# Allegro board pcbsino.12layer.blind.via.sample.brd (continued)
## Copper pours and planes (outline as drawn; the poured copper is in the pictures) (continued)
VDD_1V8 on BOTTOM: 24.2,33.97 24.91,33.97 25.32,33.57 25.32,31.61 24.99,31.28 23.28,31.28 23.08,31.48 23.08,32.91 23.33,33.16 24.02,33.16 24.15,33.29 24.15,33.92
VDD_1V8 on PWR_L6: 34.94,56.1 38.52,56.1 38.96,55.66 38.96,53.2 38.98,53.2 40.66,51.52 48.51,51.52 48.91,51.12 48.91,50.05 48.48,49.62 39.64,49.62 38.96,48.93 38.96,29.05 36.87,26.96 30.7,26.96 28.82,28.84 26.99,28.84 26.53,28.38 26.53,27.65 26.15,27.27 25.62,27.27 25.26,27.62 25.26,30.42 26.28,31.43 29.53,31.43 30.45,30.52 34,30.52 34.61,31.13 34.61,33.44 33.65,34.4 33.65,49.29 34.36,50 34.36,55.49 34.35,55.5
VDD_1V8 on SIG_L10: 23.92,24.04 23.92,26.23 24.35,26.66 24.35,27.95 23.92,28.38 23.92,34.13 24.76,34.96 26.86,34.96 27.73,34.1 28.72,34.1 29.48,34.86 34.33,34.86 34.54,35.07 35.7,35.07 35.73,35.04 36.87,35.04 37.63,35.8 37.63,37.25 38.17,37.78 39.03,37.78 40.17,36.64 40.17,29.73 36.92,26.48 34.26,26.48 32.86,25.08 30.78,25.08 30.22,25.64 29.05,25.64 28.67,25.26 28.67,23.13 27.78,22.24 27.2,22.24 26.36,23.08 26.36,23.71 26.18,23.89 25.37,23.89 25.06,23.58 24.38,23.58
VDD_3V3 on TOP: 51.66,22.34 53.71,22.34 53.76,22.29 53.76,21.73 53.74,21.7 54.17,21.27 54.25,21.27 54.35,21.17 54.35,20.41 54.22,20.28 52.42,20.28 51.96,20.74 51.96,21.32 51.55,21.73 51.55,22.24
VDD_3V3 on TOP: 9.59,66.69 9.59,63.54 9.87,63.26 11.6,63.26 11.6,64.28 11.14,64.73 11.14,66.69 11.07,66.76 9.67,66.76
VDD_3V3 on TOP: 19.98,59.07 16.45,59.07 16.2,58.81 16.2,55.77 16.35,55.61 19.52,55.61 20.18,56.27 20.18,58.86
VDD_3V3 on BOTTOM: 51.22,20.84 45.15,20.84 42.74,18.43 42.74,17.67 43.07,17.34 43.65,17.34 44.14,17.82 44.14,18.68 44.82,19.37 49.29,19.37 49.55,19.11 51.02,19.11 51.6,19.7 51.6,20.46
VDD_3V3 on BOTTOM: 23.59,21.04 24.3,21.04 24.53,20.82 24.53,17.84 24.35,17.67 22.24,17.67 21.99,17.92 21.99,19.34 23.51,20.87 23.51,20.97
VDD_3V3 on BOTTOM: 21.15,7.66 21.15,5.12 21.3,4.97 21.89,4.97 22.17,4.69 22.17,3.11 22.24,3.04 23.46,3.04 23.72,3.29 23.72,3.87 23.56,4.03 23.08,4.03 23,4.1 23,4.86 23.11,4.97 23.54,4.97 23.77,5.19 23.77,5.86 27.91,5.86 28.26,6.21 28.26,8.19 28.69,8.62 28.69,9.21 28.36,9.54 27.86,9.54 27.73,9.66 27.73,10.05 27.86,10.17 27.86,10.68 27.68,10.86 25.42,10.86 24.91,11.37 24.91,11.85 24.68,12.08 23.97,12.08 23.64,11.75 23.64,7.63 23.46,7.46 22.27,7.46 21.96,7.76 21.25,7.76
VDD_3V3 on BOTTOM: 45.08,40.25 43.02,40.25 42.66,39.89 42.66,37.99 42.92,37.73 43.48,37.73 43.6,37.86 43.6,38.39 43.96,38.75 45.1,38.75 45.23,38.88 45.23,40.09
VDD_3V3 on BOTTOM: 33.52,23.41 35.04,23.41 35.45,23.81 35.45,24.88 35.6,25.03 35.96,25.03 36.62,24.37 36.62,23.79 36.52,23.69 36.26,23.69 36.09,23.51 36.09,22.9 36.47,22.52 36.47,20.18 36.36,20.08 33.6,20.08 33.19,20.49 33.19,23.08
VDD_3V3 on BOTTOM: 20.74,59.12 16.32,59.12 16.27,59.07 16.27,55.99 16.37,55.89 17.75,55.89 18.76,56.91 20.77,56.91 20.95,57.09 20.95,58.92
VDD_3V3 on INT_L3: 26.79,6.59 24.83,8.55 24.83,10.45 24.93,10.55 25.44,10.55 26.15,11.27 28.82,11.27 30.7,9.39 30.7,8.57 30.4,8.27 28.24,8.27 27.91,8.6 27.91,9.92 27.47,10.35 26.31,10.35 26.13,10.17 26.13,8.14 26.61,7.66 27.37,7.66 27.83,7.2 27.83,6.82 27.6,6.59
VDD_3V3 on INT_L3: 13.2,65.6 9.16,65.6 8.3,64.73 8.3,60.08 8.81,59.58 12.23,59.58 12.26,59.6 15.89,55.97 15.89,55.89 19.4,55.89 19.93,56.43 19.93,58.86
VDD_3V3 on INT_L3: 31.44,31.56 34.31,31.56 34.51,31.36 34.51,30.82 35.5,29.83 37.74,29.83 38.55,30.65 39.26,30.65 39.41,30.49 39.41,29.76 39.06,29.4 39.06,28.64 38.63,28.21 38.63,27.8 38.7,27.72 42.08,27.72 42.89,26.91 42.89,22.85 42.31,22.26 40.86,22.26 40.38,22.75 40.38,23.18 39.31,24.24 38.63,24.24 38.22,24.65 38.22,26.1 37.94,26.38 37.15,26.38 36.64,26.89 35.07,26.89 33.27,25.08 33.27,22.7 32.35,21.78 29.43,21.78 29.15,22.06 29.15,23.38 29.4,23.64 30.17,23.64 30.4,23.86 30.4,25.39 29.96,25.82 28.9,25.82 28.31,25.24 28.31,22.8 27.75,22.24 25.21,22.24 25.06,22.39 25.06,23.41 24.43,24.04 24.43,26.56 24.68,26.81 24.68,27.5 23.99,28.18 23.99,31.94 24.43,32.37 25.34,32.37 26.03,31.69 28.82,31.69 29.4,32.27 31.16,32.27 31.34,32.09 31.34,31.66
VDD_3V3 on SIG_L5: 38.12,32.83 38.12,29.78 38.55,29.35 40.56,29.35 41.09,28.82 41.09,27.6 41.47,27.22 42.46,27.22 42.71,27.47 42.71,31.84 41.9,32.65 39.56,32.65 39.18,33.03 38.32,33.03
VDD_3V3 on PWR_L6: 8.3,1.84 8.3,4.03 9.42,5.14 15.43,5.14 17.64,7.35 17.64,18.2 18.66,19.22 22.9,19.22 23.56,19.88 23.56,20.71 24.2,21.35 24.91,21.35 27.25,23.69 29.43,23.69 31.89,21.22 36.69,21.22 38.07,22.59 43.88,22.59 45.53,24.24 45.53,35.29 45.23,35.6 45.23,36.41 45.53,36.72 45.53,46.37 49.52,50.36 49.52,51.4 49.72,51.6 49.72,51.63 53.26,51.63 53.53,51.35 53.53,18.35 52.75,17.56 47.46,17.56 45.64,15.74 45.64,11.6 47.41,9.82 47.41,4.1 45.95,2.64 36.35,2.64 34.74,1.03 34.74,0.64 34.48,0.38 33.65,0.38 32.74,1.28 8.86,1.28
VDD_3V3 on SIG_L8: 15.74,59.45 15.74,55.77 16.4,55.11 23.23,55.11 23.33,55.21 28.13,55.21 30.62,52.72 33.77,52.72 38.84,57.79 40.75,57.79 40.76,57.8 40.81,57.8 41.19,57.42 41.19,55.41 36.44,50.66 36.44,43.27 33.82,40.65 33.82,35.45 34.36,34.91 36.92,34.91 37.02,35.01 37.02,37.4 39.23,39.61 39.23,50.2 42.66,53.63 49.57,53.63 50.11,53.1 50.11,48.78 52.21,46.67 52.21,44.82 50.54,43.14 44.72,43.14 43.17,41.59 43.17,37.12 43.45,36.84 49.98,36.84 51.45,35.37 54.35,35.37 55.74,36.77 55.74,61.07 52.47,64.35 52.47,65.39 51.22,66.64 46.32,66.64 44.57,64.88 30.07,64.88 25.19,60.01 16.3,60.01
VDD_3V3 on SIG_L10: 26.74,6.16 23.87,9.03 23.87,10.33 24.12,10.58 25.82,10.58 26.15,10.25 26.15,9.18 28.06,7.28 28.06,6.36 27.86,6.16
VDD_CORE on TOP: 36.03,65.49 36.03,62.62 36.52,62.14 41.7,62.14 42.74,61.1 43.63,61.1 43.96,61.43 43.96,64.91 43.35,65.52 41.39,65.52 41.04,65.16 38.6,65.16 37.96,65.8 36.34,65.8
VDD_CORE on BOTTOM: 31.74,28.97 33.67,28.97 33.82,28.82 33.82,27.93 33.65,27.75 31.74,27.75 31.61,27.88 31.61,28.84
VDD_CORE on BOTTOM: 34.99,31.61 36.11,31.61 36.29,31.43 36.29,30.21 36.39,30.11 36.8,30.11 36.85,30.06 36.85,29.45 36.64,29.25 35.78,29.25 35.32,29.71 35.32,29.76 34.69,30.39 34.69,31.31
VDD_CORE on PWR_L7: 27.6,14.19 25.75,16.04 25.75,29.55 26.46,30.26 27.22,30.26 28.62,31.66 38.75,31.66 39.62,30.8 39.62,25.69 39.16,25.24 35.04,25.24 34.87,25.41 34.87,26.63 34.23,27.27 31.06,27.27 30.73,26.94 30.73,24.17 31.36,23.53 31.36,21.65 32.45,20.56 43.76,20.56 46.35,23.15 46.35,52.26 37.56,61.05 37.56,66.36 37.96,66.36 40,65.22 42.03,66.36 43.37,66.36 52.7,57.04 52.7,17.54 49.34,14.19
VDD_CORE on SIG_L8: 30.88,31.81 26.99,31.81 26,30.82 26,16.62 27.02,15.61 33.85,15.61 34.21,15.96 34.21,17.13 32.66,18.68 32.66,30.04
VDD_DSP on TOP: 20.87,66.99 27.55,66.99 28.29,66.26 28.29,63.26 28.06,63.03 26.36,63.03 24.86,64.53 21.33,64.53 20.49,65.37 20.49,66.61
VDD_DSP on BOTTOM: 32.07,26.86 34.36,26.86 34.54,26.68 34.54,25.24 34.31,25.01 33.85,25.01 33.77,24.93 33.77,24.6 33.49,24.32 31.74,24.32 31.41,24.65 31.41,25.97 31.56,26.12 31.89,26.12 31.97,26.2 31.97,26.76
VDD_DSP on BOTTOM: 20.82,66.82 27.53,66.82 28.29,66.05 28.29,63.44 27.88,63.03 26.2,63.03 25.57,63.67 25.57,64.35 25.44,64.48 21.76,64.48 20.69,65.55 20.69,66.69
VDD_DSP on PWR_L7: 31.23,27.14 34.08,27.14 34.64,26.58 34.64,25.21 34.82,25.03 39.54,25.03 39.95,25.44 39.95,37.24 40,49.52 29.02,60.49 18.31,60.49 16.65,62.14 16.65,66.79 16.98,67.12 31.13,67.12 46.07,52.18 46.07,23.33 43.65,20.92 32.66,20.92 31.54,22.03 31.54,23.74 30.93,24.35 30.93,26.84
VDD_GPU on TOP: 20.44,64.96 17.06,64.96 16.1,64 16.1,62.5 16.22,62.37 17.24,62.37 17.95,63.08 20.49,63.08 20.59,63.18 20.59,64.81
VDD_GPU on BOTTOM: 20.82,64.81 16.68,64.81 15.79,63.92 15.79,62.45 20.41,62.45 20.95,62.98 20.95,64.68
VDD_GPU on BOTTOM: 34.38,33.21 34.38,31.61 33.62,30.85 32.5,30.85 32.48,30.87 32.48,32.32 32.61,32.45 33.06,32.45 33.27,32.65 33.27,33.13 33.37,33.24 34.36,33.24
VDD_GPU on PWR_L6: 20.57,64.73 16.48,64.73 15.74,64 15.74,60.41 18.51,57.65 18.51,54.12 29.15,43.47 29.15,33.9 29.81,33.24 29.81,31.79 30.83,30.77 33.82,30.77 34.56,31.51 34.56,33.11 33.29,34.38 33.29,46.16 23.64,55.82 23.64,61.66
VDD_IVA on TOP: 16.25,55.21 16.25,52.77 17.37,51.65 17.37,50.58 17.75,50.2 19.52,50.2 19.98,50.66 19.98,53.78 19.32,54.45 18.43,54.45 17.72,55.16 17.72,55.18 17.57,55.33 16.37,55.33
VDD_IVA on BOTTOM: 18.25,53.78 20.95,53.78 21.2,53.53 21.2,52.13 20.79,51.73 16.81,51.73 16.04,52.49 16.04,54.37 16.35,54.67 16.35,55.39 16.48,55.51 17.62,55.51 17.85,55.28 17.85,54.19
VDD_IVA on BOTTOM: 26.33,31.79 27.42,31.79 27.7,31.51 27.7,29.96 27.53,29.78 26.92,29.78 26.79,29.91 26.79,30.26 26.51,30.54 26.2,30.54 26.05,30.7 26.05,31.51
VDD_IVA on PWR_L7: 24.58,30.34 26.15,30.34 26.37,30.56 27.11,30.56 28.67,32.12 28.67,47.71 20.95,55.44 16.43,55.44 16.04,55.05 16.04,51.22 19.91,47.36 22.37,47.36 23.63,46.1 23.63,43.64 24.32,42.94 24.32,30.59
VDD_IVA on SIG_L10: 25.06,47.08 25.06,46.29 25.47,45.89 26.43,45.89 26.53,45.99 26.53,46.83 26.15,47.21 25.19,47.21
VDD_MPU on TOP: 34.79,48.04 34.79,45.43 35.09,45.12 40.5,45.12 40.83,45.45 40.83,48.02 40.53,48.32 35.07,48.32
VDD_MPU on BOTTOM: 26.94,28.61 27.58,28.61 28.87,27.32 28.87,27.06 29.02,26.91 29.86,26.91 30.04,26.73 30.04,25.03 29.96,24.96 29.51,24.96 29.18,25.29 29.18,25.34 28.59,25.34 28.31,25.06 28.31,24.7 28.29,24.68 27.5,24.68 27.35,24.83 27.35,25.16 27.14,25.36 26.79,25.36 26.66,25.49 26.66,28.33
VDD_MPU on BOTTOM: 35.81,49.19 41.04,49.19 41.19,49.04 41.19,48.27 40.56,47.64 40.56,42.79 40.33,42.56 39.03,42.56 37.99,43.6 37.99,44.82 37.89,44.92 35.96,44.92 35.45,45.43 35.45,48.83
VDD_MPU on PWR_L6: 26.38,26.89 26.38,24.78 27.27,23.89 29.71,23.89 31.94,21.65 36.67,21.65 37.74,22.72 43.48,22.72 45.33,24.57 45.33,35.27 45.08,35.52 45.08,36.51 45.33,36.77 45.33,47.77 44.14,48.96 39.87,48.96 39.21,48.3 39.21,28.94 37.13,26.86 30.47,26.86 28.72,28.61 27.09,28.61 26.59,28.11 26.59,27.09
VDD_RTC on SIG_L8: 29.02,34.86 29.79,34.86 30.22,35.29 30.22,38.47 35.48,43.73 35.48,51.04 39.39,54.95 40.2,54.95 40.61,55.36 40.61,56.5 39.95,57.16 38.68,57.16 33.34,51.83 33.34,44.56 28.34,39.56 28.34,35.55
VDD_SD on BOTTOM: 35.45,33.29 35.45,32.04 35.58,31.92 37.46,31.92 37.76,32.22 38.07,32.22 40.33,34.48 40.33,34.84 40.5,35.01 42.13,35.01 42.33,35.22 42.33,36.26 41.93,36.67 40.07,36.67 39.87,36.46 38.85,36.46 37.02,34.63 37.02,33.97 36.54,33.49 35.65,33.49
VDD_SD on PWR_L6: 41.24,58.86 34,58.86 32.83,57.7 32.83,56.12 33.14,55.82 34.59,55.82 35.12,56.35 40.17,56.35 44.39,52.13 48.91,52.13 49.22,52.44 49.22,53.73 48.53,54.42 45.69,54.42
VDD_SD on SIG_L8: 49.45,52.87 42.87,52.87 39.92,49.92 39.92,36 40.78,35.14 42.33,35.14 42.99,35.8 42.99,46.14 42.31,46.83 42.31,48.81 43.1,49.59 47.54,49.59 49.6,51.65 49.6,52.72
VDDA_1V8_PHY_LDO3 on BOTTOM: 24.86,49.26 23.87,49.26 22.75,48.15 22.75,45.45 22.98,45.23 24.25,45.23 24.43,45.4 24.43,47.03 25.06,47.66 25.42,47.66 25.47,47.71 25.47,48.65
VDDA_1V8_PHY_LDO3 on INT_L3: 28.34,52.16 27.17,52.16 24.91,49.9 23.92,49.9 23.79,49.77 23.79,48.4 23.87,48.32 25.93,48.32 27.55,49.95 28.16,49.95 28.59,50.38 28.59,51.91
VDDA_1V8_PHY_LDO3_F on BOTTOM: 24.81,44.03 23.31,44.03 23.23,43.96 23.23,41.24 23.61,40.86 25.67,40.86 25.8,40.98 25.8,43.04
VDDA_1V8_PHY_LDO3_F on INT_L3: 24.63,42.94 24.63,42.35 30.14,36.84 30.14,32.75 30.5,32.4 31.23,32.4 31.51,32.12 31.51,31.79 31.61,31.69 32.22,31.69 33.27,32.73 33.27,36 30.01,39.26 28.92,39.26 27.09,41.08 27.09,42.08 25.98,43.19 24.88,43.19
VDDA_1V8_PHY_LDO4 on BOTTOM: 20.57,47.82 20.57,48.6 22.29,50.33 24.83,50.33 25.49,49.67 26.56,49.67 27.04,50.15 27.04,50.89 27.42,51.27 28.13,51.27 28.26,51.14 28.26,49.29 27.78,48.81 25.44,48.81 24.83,49.42 23.84,49.42 22.14,47.71 20.67,47.71
VDDA_1V8_PHY_LDO4_F on BOTTOM: 20.29,46.5 21.4,46.5 21.63,46.27 21.63,43.4 20.92,42.69 20.92,41.87 20.67,41.62 19.91,41.62 19.6,41.92 19.6,43.04 19.98,43.42 19.98,46.19
VDDA_1V8_PHY_LDO4_F on SIG_L8: 20.21,42.43 18.36,42.43 17.9,41.97 17.9,36 21.76,32.14 31.21,32.14 31.44,32.37 31.44,33.34 30.42,34.35 27.53,34.35 27.07,34.81 22.88,34.81 21.1,36.59 21.1,41.54
VDDA_1V8_PLL on BOTTOM: 39.01,42.3 39.01,41.44 39.11,41.34 42,41.34 42.38,41.72 42.38,42.84 42.23,42.99 41.44,42.99 40.89,42.43 39.13,42.43
VDDA_1V8_PLL on SIG_L10: 28.31,36.64 28.31,48.96 37.13,57.77 43.32,57.77 43.4,57.7 43.4,57.09 42.49,56.17 38.02,56.17 36.53,54.69 36.53,52.5 35.58,51.55 34.18,51.55 30.19,47.56 30.19,44.82 29.23,43.85 29.23,37.25 28.95,36.97 28.95,36.64 28.82,36.51 28.44,36.51
VDDA_1V8_PLL_F on BOTTOM: 39.11,40.15 40.3,40.15 40.43,40.02 40.43,37.17 39.79,36.54 39.16,36.54 38.9,36.79 38.9,39.94
VDDA_1V8_PLL_F on BOTTOM: 27.63,29.68 27.63,28.72 28.64,27.7 29.68,27.7 30.27,28.28 31.23,28.28 31.34,28.38 31.34,28.92 31.18,29.07 30.5,29.07 30.19,28.77 28.69,28.77 28.39,29.07 28.39,29.38 27.98,29.78 27.73,29.78
VDDA_1V8_PLL_F on GND_L11: 27.75,29.83 28.13,29.83 28.64,29.32 31.84,29.32 38.63,36.11 38.63,37.91 39.03,38.32 40.33,38.32 40.4,38.24 40.4,34.63 32.76,26.99 28.8,26.99 27.6,28.18 27.6,29.68
VDDS_DDR on TOP: 2.2,41.69 2.2,39.94 2.71,39.43 6.47,39.43 6.52,39.48 6.52,41.06 5.78,41.8 2.3,41.8
VDDS_DDR on TOP: 11.68,60.95 11.68,60.34 11.37,60.03 9.36,60.03 9.34,60.06 8.02,58.74 8.02,53.35 7.43,52.77 3.85,52.77 3.4,52.31 3.4,50.25 3.93,49.72 16.48,49.72 16.68,49.92 16.68,51.58 15.71,52.54 12.03,52.54 11.19,53.38 11.19,58.38 12.08,59.27 12.08,61 12.03,61.05 11.78,61.05
VDDS_DDR on TOP: 12.89,8.78 14.83,8.78 15.05,8.55 15.05,6.41 14.62,5.98 12.06,5.98 11.85,6.19 11.85,7.73
VDDS_DDR on TOP: 21.4,47.82 21.4,45.07 21.73,44.74 26.46,44.74 26.46,47.77 26.1,48.12 21.71,48.12
VDDS_DDR on TOP: 2.1,19.47 2.1,17.08 2.51,16.68 16.53,16.68 17.06,17.21 17.06,19.37 16.48,19.95 13,19.95 12.36,19.32 10.3,19.32 9.06,18.07 6.8,18.07 6.06,18.81 4.92,18.81 4.18,19.55 2.18,19.55
VDDS_DDR on BOTTOM: 23.92,26.48 23.92,25.87 24.07,25.72 25.29,25.72 25.72,26.15 25.72,26.51 25.62,26.61 24.05,26.61
VDDS_DDR on BOTTOM: 24.99,35.37 24.99,34.33 24.86,34.2 24.12,34.2 24.02,34.3 24.02,35.09 24.38,35.45 24.91,35.45
VDDS_DDR on BOTTOM: 25.65,23.69 23.89,23.69 23.28,23.08 23.28,22.14 23.46,21.96 23.89,21.96 24.27,22.34 24.27,22.62 24.5,22.85 25.59,22.85 25.82,23.08 25.82,23.51
VDDS_DDR on BOTTOM: 8.3,44.41 16.17,44.41 16.88,43.7 16.88,37.78 16.17,37.07 16.17,32.58 17.54,31.2 17.54,29.73 15,27.19 15,26.86 13.91,25.77 8.2,25.77 7.97,26 7.97,27.39 9.77,29.2 9.77,33.16 10.56,33.95 10.56,36.13 10.13,36.56 9.52,36.56 9.44,36.64 9.44,39.79 9.59,39.94 9.59,42.53 9.44,42.69 8.25,42.69 8.04,42.89 8.04,44.16
VDDS_DDR on BOTTOM: 9.19,5.8 14.39,5.8 15.05,6.46 15.05,8.83 15.03,8.85 10.38,8.85 9.82,8.29 9.82,6.87 9.54,6.59 9.06,6.59 8.91,6.44 8.91,6.08
VDDS_DDR on BOTTOM: 8.42,21.22 17.52,21.22 18.36,22.06 19.12,22.06 19.37,21.81 19.37,18.38 17.34,16.35 17.34,7.73 17.31,7.71 9.85,7.71 9.69,7.86 9.69,8.12 8.81,9 8.81,9.61 8.93,9.74 9.29,9.74 9.72,10.17 9.72,11.11 10.08,11.47 11.29,11.47 11.9,12.08 11.9,13.91 11.47,14.34 10.38,14.34 9.72,15 9.72,18.76 8.17,20.31 8.17,20.97
VDDS_DDR on INT_L3: 23.69,23.33 23.66,23.33 23.28,22.95 23.28,22.57 23.74,22.11 24.05,22.11 24.53,22.59 24.53,22.64 24.6,22.72 24.83,22.72 24.96,22.85 24.96,23.25 24.68,23.53 23.89,23.53
VDDS_DDR on INT_L3: 24.3,34.89 24.3,33.74 26.15,31.89 28.47,31.89 29.05,32.47 29.05,33.31 28.13,34.23 27.58,34.23 26.61,35.19 26.61,35.22 24.63,35.22
VDDS_DDR on INT_L3: 21.51,47.69 21.51,45.81 22.78,44.54 23.72,44.54 23.84,44.67 23.84,47.49 23.41,47.92 21.73,47.92
VDDS_DDR on PWR_L6: 4.79,57.01 2.2,54.42 2.2,7.15 3.52,5.83 14.85,5.83 17.16,8.14 17.16,18.73 17.9,19.47 22.65,19.47 23.28,20.1 23.28,20.97 23.91,21.59 24.77,21.59 26,22.82 26,26.66 25.11,27.55 25.11,30.59 26.26,31.74 29.38,31.74 29.56,31.92 29.56,32.98 28.8,33.74 28.8,43.27 17.64,54.42 14.55,54.42 11.96,57.01
VDDS_DDR on SIG_L10: 24.02,23.38 23.74,23.38 23.44,23.08 23.44,22.34 23.64,22.14 24.5,22.14 25.14,22.77 25.75,22.77 25.82,22.85 25.82,23.2 25.65,23.38 25.34,23.38 25.14,23.18 24.22,23.18
ETH0_DVDD33 on BOTTOM: 45.71,39.79 45.71,36.44 46.4,35.75 49.06,35.75 49.12,35.8 49.12,36.18 48.76,36.54 47.92,36.54 47.13,37.33 47.13,39.31 46.47,39.97 45.89,39.97
ETH0_VDD10 on BOTTOM: 49.72,29.96 47.72,29.96 47.16,29.4 44.8,29.4 44.57,29.17 44.57,28.05 44.72,27.9 47.18,27.9 47.74,27.34 48.81,27.34 49.8,28.33 49.8,29.88
ETH0_VDDREG33 on BOTTOM: 46.12,35.14 47.16,35.14 47.26,35.04 47.26,33.08 47.49,32.86 48.15,32.86 48.2,32.8 48.2,32.07 48.12,31.99 46.02,31.99 45.86,32.14 45.86,34.89
ETH1_AVDD33 on BOTTOM: 49.57,18.68 49.57,16.24 49.72,16.09 50.79,16.09 50.94,16.24 50.94,16.6 51.12,16.78 52.11,16.78 52.37,16.52 52.37,14.95 53.08,14.24 53.08,12.41 52.39,11.72 52.39,11.14 52.44,11.09 53.23,11.09 53.94,11.8 53.94,16.35 52.52,17.77 51.12,17.77 50.56,18.33 50.56,18.78 50.51,18.83 49.72,18.83
ETH1_DVDD10 on BOTTOM: 46.35,18.78 49.01,18.78 49.09,18.71 49.09,17.59 48.91,17.41 46.42,17.41 46.22,17.62 46.22,18.66
ETH1_VDD10 on TOP: 39.11,8.37 43.3,8.37 43.65,8.01 43.65,6.9 43.3,6.54 37.99,6.54 37.79,6.74 37.79,7.86 37.86,7.94 38.68,7.94
ETH1_VDD10 on INT_L3: 38.19,7.28 38.19,6.57 38.47,6.29 41.55,6.29 42.31,7.05 44.98,7.05 45.58,6.44 46.52,6.44 46.63,6.54 46.63,7.79 46.45,7.96 38.88,7.96
ETH1_VDDREG33 on BOTTOM: 46.5,13.58 45.89,13.58 45.71,13.4 45.71,9.92 45.89,9.74 46.55,9.74 47.06,10.25 47.06,12.54 46.6,12.99 46.6,13.48
LDO_VRTC on TOP: 37.3,54.12 38.75,54.12 39.08,54.45 39.08,55.18 38.8,55.46 38.35,55.46 37.91,55.03 37.25,55.03 36.97,54.75 36.97,54.45
LDO_VRTC on BOTTOM: 32.55,40.73 32.55,37.43 31.67,36.54 31.67,35.27 31.26,34.86 30.7,34.86 30.5,35.07 30.5,36.69 31.59,37.78 31.59,40.73 31.69,40.83 32.45,40.83
LDO_VRTC on SIG_L8: 30.8,35.5 32.22,35.5 33.34,34.38 33.34,31.43 35.48,29.3 35.48,19.75 37.91,17.31 37.91,5.14 37.66,4.89 36.77,4.89 36.62,5.04 36.62,16.35 33.9,19.06 33.9,29.1 32.2,30.8 32.2,33.87 31.56,34.51 30.75,34.51 30.62,34.63 30.62,35.32
LDO_VRTC on SIG_L10: 38.22,55 39.21,55 39.39,54.83 39.39,53.48 36.75,50.84 36.06,50.84 34.41,49.19 34.41,46.8 31.21,43.6 31.21,41.9 32.38,40.73 32.38,40.37 32.05,40.04 31.31,40.04 29.51,41.85 29.51,43.83 33.27,47.59 33.27,49.24 38.09,54.06 38.09,54.88
SMPS1_SW on TOP: 32.5,52.44 32.15,52.44 32.05,52.34 32.05,49.21 32.5,48.76 33.49,48.76 33.7,48.96 33.7,49.49 33.55,49.64 33.14,49.64 32.66,50.13 32.66,52.29
SMPS1_SW on BOTTOM: 33.98,49.62 31.94,49.62 31.69,49.37 31.69,45.5 31.92,45.28 33.95,45.28 34.18,45.5 34.18,49.42
SMPS2_SW on TOP: 31.18,52.44 31.18,49.85 30.73,49.39 30.73,45.56 31.03,45.25 33.24,45.25 33.44,45.45 33.44,47.87 33.01,48.3 32.3,48.3 31.82,48.78 31.82,52.44 31.74,52.51 31.26,52.51
SMPS3_SW on TOP: 28.74,52.39 28.74,49.77 27.32,48.35 27.32,45.45 27.65,45.12 29.58,45.12 30.22,45.76 30.22,48.98 29.53,49.67 29.53,52.36 29.4,52.49 28.85,52.49
SMPS4_SW on TOP: 30.34,58.46 30.34,62.04 29.33,63.06 29.33,65.85 29.48,66 31.46,66 31.69,65.77 31.69,61.91 31.11,61.33 31.11,58.43 31.03,58.36 30.45,58.36
SMPS5_SW on TOP: 29.56,58.46 29.56,60.52 29.23,60.85 29.23,61.76 29.35,61.89 29.96,61.89 30.17,61.68 30.17,58.41 30.14,58.38 29.63,58.38
SMPS5_SW on BOTTOM: 29.53,66.43 31.49,66.43 31.69,66.23 31.69,61.76 30.45,60.52 29.58,60.52 29.33,60.77 29.33,66.23
SMPS6_SW on TOP: 25.37,57.42 26.92,57.42 27.04,57.29 27.04,56.68 26.99,56.63 24.78,56.63 23.99,57.42 23.99,57.82 23.13,58.69 21.78,58.69 21.23,59.25 18.08,59.25 17.54,59.78 17.54,61.91 17.67,62.04 21.45,62.04 21.76,61.74 21.76,61 22.14,60.62 23.59,60.62 24.78,59.42 24.78,58
SMPS7_SW on TOP: 32.73,58.48 32.73,61.48 32.12,62.09 32.12,65.95 32.17,66 34.41,66 34.56,65.85 34.56,63.08 33.6,62.12 33.6,58.53 33.44,58.38 32.83,58.38
SMPS8_SW on TOP: 26.92,53.45 23.54,53.45 23.05,53.94 21.33,53.94 21.1,53.71 21.1,50.79 21.35,50.53 23.16,50.53 23.36,50.74 23.36,52.03 23.94,52.62 26.89,52.62 27.02,52.74 27.02,53.35
SMPS9_SW on TOP: 21.25,58.38 21.25,55.46 21.66,55.05 26.76,55.05 26.97,55.26 26.97,55.54 26.71,55.79 24.76,55.79 23.51,57.04 23.51,57.93 22.98,58.46 21.33,58.46
VREF_DDR on TOP: 13.25,63.56 13.25,64.4 13.5,64.66 14.06,64.66 14.47,65.06 14.47,65.65 14.55,65.72 16.5,65.72 16.68,65.55 16.68,64.88 16.22,64.43 15.66,64.43 14.93,63.69 13.81,63.69 13.58,63.46 13.35,63.46
VREF_DDR on SIG_L5: 26.76,34.02 27.42,34.02 27.75,33.69 27.75,28.87 26.92,28.03 26.92,27.57 25.85,26.51 23.94,26.51 23.56,26.89 23.56,27.42 23.72,27.57 24.25,27.57 25.7,29.02 25.7,31.46 26.64,32.4 26.64,33.9
VREF_DDR on PWR_L7: 16.68,65.62 8.4,65.62 6.54,63.77 6.54,58.26 6.82,57.98 6.82,45.58 5.53,44.29 5.53,9.61 6.7,8.45 9.52,8.45 11.14,10.07 11.14,20.46 15.77,25.08 24.38,25.08 24.96,25.67 24.96,28.69 23.94,29.71 12.21,29.71 11.27,30.65 11.27,62.83 11.7,63.26 16.5,63.26 16.91,63.67 16.91,65.39
VSYS_5V0 on TOP: 52.54,63.08 52.54,54.7 52.72,54.52 54.63,54.52 54.93,54.83 54.93,63.08 54.68,63.34 52.8,63.34
VSYS_5V0 on TOP: 26.89,57.59 25.44,57.59 24.96,58.08 24.96,59.04 25.11,59.2 25.67,59.2 26.97,57.9 26.97,57.67
VSYS_5V0 on TOP: 33.67,56.99 33.67,57.93 34.15,58.41 34.41,58.41 34.74,58.08 34.74,57.47 34.05,56.78 33.88,56.78
VSYS_5V0 on TOP: 25.29,54.85 27.04,54.85 27.4,54.5 27.4,54.12 26.89,53.61 25.39,53.61 25.14,53.86 25.14,54.7
VSYS_5V0 on TOP: 25.16,56.5 26.84,56.5 27.4,55.94 27.4,55.64 27.35,55.59 27.02,55.59 26.71,55.89 25.14,55.89 25.06,55.97 25.06,56.4
VSYS_5V0 on TOP: 29.4,60.54 29.4,58.56 29.25,58.41 28.87,58.41 28.52,58.76 28.52,60.54 28.64,60.67 29.28,60.67
VSYS_5V0 on TOP: 29.76,52.51 29.76,50.05 29.99,49.82 30.7,49.82 30.93,50.05 30.93,52.39 30.5,52.82 30.07,52.82
VSYS_5V0 on TOP: 31.28,58.59 31.28,61.18 31.72,61.61 32.28,61.61 32.58,61.3 32.58,58.51 32.43,58.36 31.51,58.36
VSYS_5V0 on TOP: 32.83,51.65 32.83,50.25 33.19,49.9 33.65,49.9 33.77,50.03 33.77,51.19 33.21,51.75 32.94,51.75
VSYS_5V0 on BOTTOM: 32.05,62.93 33.62,62.93 33.8,62.75 33.8,60.44 32.83,59.47 31.64,59.47 31.21,59.91 31.21,60.92 32,61.71 32,62.88
VSYS_5V0 on BOTTOM: 32.88,53.12 30.32,53.12 30.01,52.82 30.01,51.7 29.68,51.37 28.74,51.37 28.44,51.07 28.44,50.08 28.69,49.82 30.6,49.82 30.78,50 30.78,51.42 30.93,51.58 32.66,51.58 33.19,52.11 33.19,52.82
VSYS_5V0 on BOTTOM: 32.96,51.32 32.96,50.05 33.19,49.82 34.79,49.82 35.15,50.18 35.15,51.58 35.02,51.7 33.34,51.7
VSYS_5V0 on BOTTOM: 27.58,61.66 27.58,58.99 27.86,58.71 30.57,58.71 30.65,58.79 30.65,60.13 30.5,60.29 29,60.29 28.97,60.31 28.97,61.66 28.87,61.76 27.68,61.76
VSYS_5V0 on BOTTOM: 24.12,60.57 24.12,52.9 24.38,52.64 26.18,52.64 26.36,52.82 26.36,53.71 26.51,53.86 27.27,53.86 27.45,54.04 27.45,55.92 26.61,56.76 26.61,58.41 26.38,58.64 25.95,58.64 25.85,58.74 25.85,59.12 25.7,59.27 25.32,59.27 25.14,59.45 25.14,60.57 25.04,60.67 24.22,60.67
VSYS_5V0 on BOTTOM: 33.93,58.43 33.93,56.93 33.98,56.88 35.27,56.88 35.98,56.17 37.94,56.17 37.94,57.54 37.81,57.67 35.86,57.67 35.53,58 34.82,58 34.61,58.2 34.61,58.36 34.43,58.53 34.03,58.53
VSYS_5V0 on INT_L3: 50.18,61.28 54.5,61.28 54.63,61.15 54.63,58.28 54.2,57.85 54.2,55.89 54.22,55.87 54.22,55.69 53.26,54.72 50.13,54.72 49.09,55.77 49.09,60.19
VSYS_5V0 on SIG_L5: 23.97,60.49 23.97,50 25.44,48.53 39.08,48.53 44.09,53.53 50.18,53.53 51.17,54.52 51.17,61.23 50.74,61.66 37.71,61.66 36.69,62.67 26.15,62.67
VSYS_5V0 on PWR_L6: 55.59,2.58 53.94,4.23 53.94,51.45 53.92,51.45 53.15,52.21 50.03,52.21 49.78,52.46 49.78,54.5 49.37,54.9 45.86,54.9 41.8,58.97 33.85,58.97 32.66,57.77 32.66,56.12 33.82,54.95 33.82,50.08 33.53,49.78 30.05,49.78 24.83,55 24.83,65.16 25.82,66.15 36.82,66.15 38.32,64.66 47.08,64.66 47.63,64.11 53.9,64.11 56.56,66.76 59.25,66.76 59.43,66.59 59.43,25.68 56.5,25.68 55.62,24.8 56.5,23.92 59.43,23.92 59.43,3.24 58.77,2.58
VTT_DDR on TOP: 12.23,61.13 12.23,55.82 11.5,55.08 11.5,53.96 11.85,53.61 14.06,53.61 14.22,53.76 14.22,58.46 14.14,58.53 14.14,59.42 13.78,59.78 12.97,59.78 12.56,60.19 12.56,61.1 12.54,61.13
VTT_DDR on BOTTOM: 2.18,12.28 2.18,10.38 1.24,9.44 1.24,6.69 1.46,6.46 3.37,6.46 3.5,6.59 3.5,7.15 3.29,7.35 2.66,7.35 2.46,7.56 2.46,8.67 3.04,9.26 3.04,11.39 3.32,11.67 3.32,12.1 3.07,12.36 2.25,12.36
VTT_DDR on BOTTOM: 3.62,18.4 2.66,18.4 1.92,19.14 1.92,27.55 3.57,29.2 3.57,29.55 3.45,29.68 2.05,29.68 1.74,29.99 1.74,33.41 2.25,33.92 3.12,33.92 3.14,33.9 3.47,34.23 3.47,35.17 3.34,35.29 2.2,35.29 2.02,35.47 2.02,39.41 2.25,39.64 4.89,39.64 5,39.74 5,40.88 4.74,41.14 4.16,41.14 2.02,43.27 2.02,49.75 5.58,53.3 13.35,53.3 14.04,53.99 14.04,56.81 13.58,57.26 5.27,57.26 0.68,52.67 0.68,15.35 2.2,13.83 2.2,12.15 2.71,11.65 4.26,11.65 4.44,11.82 4.44,12.94 4.28,13.09 3.45,13.09 3.27,13.27 3.27,14.85 2.4,15.71 2.4,17.44 2.73,17.77 3.67,17.77 3.73,17.82 3.73,18.3
VUSB_3V3 on BOTTOM: 34.99,39.05 34.99,36.87 34.46,36.34 34.46,34.23 33.55,33.31 32.53,33.31 32.35,33.49 32.35,34.4 32.55,34.61 33.11,34.61 33.29,34.79 33.29,35.4 32.73,35.95 32.73,39.1 33.01,39.38 34.66,39.38
VUSB_3V3 on PWR_L7: 31.67,32.83 33.01,32.83 35.17,34.99 35.17,49.49 36.03,50.36 36.03,53.15 34.99,54.19 34.23,54.19 33.04,53 33.04,37 31.23,35.19 31.23,33.26
N31526000 on BOTTOM: 48.07,31.61 44.77,31.61 44.62,31.46 44.62,30.34 44.82,30.14 47.95,30.14 48.25,30.44 48.25,31.43
N31526000 on SIG_L10: 47.69,31.53 47.69,30.44 47.85,30.29 48.68,30.29 48.96,30.57 48.96,30.98 48.66,31.28 48.28,31.28 48.18,31.38 48.18,31.48 48.1,31.56 47.72,31.56
N31599735 on TOP: 46.55,13.5 45.41,13.5 44.82,12.92 44.82,12.48 44.01,11.67 41.88,11.67 40.71,10.5 40.71,9.33 40.96,9.08 43.65,9.08 43.86,9.28 43.86,9.64 45.43,11.21 45.43,12.61 46.07,13.25 46.52,13.25 46.6,13.32 46.6,13.45

Small or netless copper shapes (teardrops, artwork), in the pictures only: 2 on TOP, 1 on BOTTOM

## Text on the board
BOTTOM: LAYER 12 | SOLDER
Board Geometry/Soldermask Bottom: SMS
Ref Des/Silkscreen Bottom: A
User.Comments: CR_UNNAMED_1
TOP: LAYER 1 | COMPONENT
Board Geometry/Soldermask Top: SMC
Ref Des/Silkscreen Top: D | B | A | C | STT-SOM-AM5728_V1.0
GND_L2: LAYER 2 | GROUND
INT_L3: LAYER 3 | SIGNAL
GND_L4: LAYER 4 | GROUND
SIG_L5: LAYER 5 | SIGNAL
PWR_L6: LAYER 6 | SIGNAL
SIG_L8: LAYER 8 | GROUND
SIG_L10: LAYER 10 | SIGNAL
GND_L11: LAYER 11 | GROUND
DISPLAY_TOP: SERIAL DEBUG | POWER | SD/eMMC | SATA/SD | FAN | DC | 3.3V | 12V | GND | 5V | AM572X | CURRENT MON | DC IN | RESET | HDMI | uSD | USB3_1 | USB_2/3 | SPC
DISPLAY_BOTTOM: JTAG | uSD | SPS
USER_PART_NUM_TOP: TSLKC
USER_PART_NUM_BOTTOM: BSLKC
User.15: TSLK
User.16: BSLK
User.17: ASSEMBLY_TOP
User.18: ASSEMBLY_BOTTOM
User.22: LAYER 1 - PRIMARY SIDE - SIGNAL | LAYER 2 - GROUND PLANE | LAYER 3 - INT. SIGNAL | LAYER 4 - GROUND PLANE | LAYER 5 - INT. SIGNAL | LAYER 6 - POWER PLANE | LAYER 7 - POWER PLANE | LAYER 8 - INT. SIGNAL | LAYER 9 - GROUND PLANE | LAYER 10- INT. SIGNAL | LAYER 11- GROUND PLANE | LAYER 12- SECONDARY SIDE - SIGNAL | COPPER WEIGHT | HALF+PLATING | (OZ) | 50ohm SINGLE ENDED | IMPEDANCE CONTROL | +/- 10% | TRACE WIDTH | TRACE WIDTH / SPACE | 90ohm DIFFERENTIAL | 100ohm DIFFERENTIAL | FINISHED AS SMOOTH WALL BY VENDOR. | PROCESS NOTES: | 2. APPLY LPI SOLDERMASK OVER BARE COPPER (SMOBC), | COLOR: BLACK. SOLDERMASK SHALL CONFIRM TO IPC-SM-840. | CLASS H. CURRENT REV. | 3. SOLDERMASK ARTWORK HAS ZERO (0) OVERSIZED PADS. | FABRICATION VENDOR IS ALLOWED TO ADJUST THE COMPONENT | SOLDERMASK PADS TO MEET THEIR TOOLING REQUIREMENTS. | 4. APPLY LPI SILKSCREEN OR EQUIVALENT PER THE ARTWORK. | COLOR: ORANGE. | 1. PLATE ALL EXPOSED AREAS WITH ELECTROLESS | IMMERSION GOLD, NICKEL 150 MICROINCHES THK MIN | GOLD 5-15 MICROINCHES THK MIN. | SUPPLIED IPC-D-356 NETLIST. | 1. ALL DIMENSIONS ARE IN INCHES, UNLESS | OTHERWISE NOTED. | 2. THE PWB SHALL BE FABRICATED TO IPC-6012, | CLASS 2 AND WORKMANSHIP SHALL CONFORM TO | IPC-A-600, CLASS 2. CURRENT REVISIONS. | 3. BOARD MATERIAL SHALL BE 180 Tg/350 Td ISOLA FR-370HR | OR EQUIVALENT, RoHS COMPLIANT AND LEAD FREE | ASSEMBLY CAPABLE.  BOARD MATERIAL SHALL | MEET OR EXCEED IPC-4101B. COLOR: NATURAL. | 4. BOARD MATERIAL & CONSTRUCTION TO BE U.L. | APPROVED AND MARKED ON THE FINISHED BOARD. | 5. MINIMUM COPPER WALL THICKNESS OF PLATED-THRU | HOLES TO BE .001 INCH, WITH A MINIMUM | ANNULAR RING OF .002 INCH. | 6. OVERALL BOARD THICKNESS TO BE .062 +/- 10% | AND APPLIES AFTER ALL LAMINATION AND PLATING | PROCESSES, MEASURED FROM COPPER TO COPPER. | 7. MAX. WARP & TWIST TO BE .0075 INCHES PER INCH. | 8. BOARD MUST BE ELECTRICALLY TESTED USING | 9. FOR BACKDRILL INFO. SEE GERBER FILE (BACKDRILL_12-4.ART). | FAB NOTES: | ALL DIMENSIONS IN MILS | LAYER# | LAYER STACK-UP | 1 | 4.72 | 3.70 | 5.00/9.00 | 4.50/10.00 | 4.00/10.00 | 3.70/12.00 | SCALE=NONE | o
User.23: C78 | C200 | C201 | C57 | C52 | C79 | C86 | C85 | C146 | C128 | C154 | C147 | C182 | C198 | C56 | C66 | C87 | C88 | C91 | C90 | C129 | C89 | C71 | C273 | C192 | C185 | C498 | C68 | C62 | C84 | C77 | C82 | C83 | C153 | C143 | C177 | C69 | C150 | C142 | C145 | C183 | C155 | C51 | C74 | C60 | C59 | C204 | C75 | C152 | C72 | C144 | C199 | C141 | C203 | C166 | 6 | 1 | R290 | C399 | R288 | R286 | U27 | U3 | U1 | C9 | C8 | C2 | 3 | R291 | Q5 | D2 | D1 | C390 | R287 | C400 | R335 | U20 | R289 | C398 | C391 | C392 | R285 | Q6 | U7 | TP20 | TP21 | C292 | C306 | C347 | C363 | C283 | 4 | C318 | C335 | C376 | 2 | C284 | R4 | R2 | L1 | C293 | C307 | C319 | C336 | C348 | C364 | C377 | R51 | L2 | TP4 | U2 | C295 | U13 | 7 | 9 | C247 | 28 | 11 | 12 | 10 | 13 | U18 | Y2 | L8 | N | R231 | R244 | M | U21 | L | K | C252 | 22 | J | 24 | 23 | H | L7 | G | R395 | F | E | Y3 | D | C | B | L6 | A | Q4 | 5 | 25 | C50 | C442 | C454 | U31 | J5 | U33 | AH | AF | AD | AB | W | U | R | AG | AE | AC | AA | Y | V | T | P | 15 | R398 | R399 | U6 | C241 | C242 | C239 | C244 | R202 | R206 | U17 | 49 | 64 | 48 | 14 | 18 | 33 | 16 | Y5 | 17 | 32 | R93 | R389 | D24 | R298 | R293 | U28 | C403 | R292 | L16 | Y6 | R120 | R390 | R181 | R180 | R193 | R194 | R239 | R195 | R190 | R182 | R183 | R187 | R189 | R188 | R192 | R196 | R197 | R191 | 30 | R396 | R397 | C443 | C473 | R401 | 31 | 60 | FB7 | R119 | C232 | C233 | C234 | R122 | R123 | R317 | U32 | R200 | R203 | R201 | L19 | L17 | R68 | R91 | FB5 | L18 | C414 | C412 | C407 | C405 | R296 | C401 | C229 | C225 | C224 | C440 | U42 | R297 | R294 | C408 | C228 | Q2 | C402 | U16 | U30 | U29 | C226 | C227 | FB8 | FB6 | C492 | C489 | C493 | C488 | C487 | C270 | R255 | C217 | C218 | C219 | R95 | R96 | R316 | FB3 | R92 | C486 | C481 | FB1 | R90 | R69 | R328 | C491 | C214 | C211 | C209 | R31 | C494 | C483 | Y7 | C213 | Q1 | C246 | C482 | C490 | C235 | C240 | C210 | TP17 | TP18 | C212 | FB2 | FB4 | R430 | Y1 | R130 | R131 | R132 | R128 | R129 | R126 | R124 | R125 | C130 | C245 | C237 | C238 | C54 | C131 | C53 | R127 | C63 | C64 | C70 | C80 | U34 | R42 | R44 | P7 | C122 | C97 | R140 | U10 | R138 | R134 | R139 | R135 | R145 | R133 | R152 | R149 | R153 | R428 | R424 | C119 | C120 | C114 | C121 | R41 | 20 | U9 | C28 | C20 | C16 | 19 | C94 | C117 | C118 | C187 | C188 | C19 | R24 | R32 | C27 | C195 | C65 | C126 | C116 | C115 | C134 | C194 | C124 | C55 | C421 | Y9 | C110 | C67 | C34 | R30 | C26 | C29 | C21 | C22 | C25 | C18 | C17 | R421 | P4 | C125 | C149 | C243 | C236 | C61 | C58 | TP6 | R411 | C139 | C76 | C499 | C95 | C186 | C172 | C173 | C191 | C176 | C264 | C265 | C170 | C162 | C164 | C181 | C262 | C196 | C175 | C169 | C96 | C274 | TP8 | TP9 | C159 | C43 | R22 | R214 | C48 | C46 | C23 | R20 | R21 | R16 | C161 | C174 | C165 | C248 | C168 | C160 | C113 | FB9 | C81 | TP7 | TP5 | C179 | C156 | TP13 | R56 | C163 | R273 | R274 | R334 | U8 | C180 | R58 | C111 | R235 | C255 | R37 | C112 | R420 | R429 | C350 | C327 | C387 | C369 | C312 | C341 | C361 | R230 | R233 | R10 | R276 | R234 | C256 | R12 | R13 | R226 | R14 | C1 | C7 | C250 | R5 | F1 | C394 | C430 | C435 | R9 | R11 | C13 | C432 | R3 | R6 | C4 | C251 | Y8 | C393 | C395 | C396 | C397 | C428 | R228 | C389 | C429 | C434 | C472 | R400 | C474 | R402 | D3 | D4 | D5 | D6 | D7 | D29 | D40 | Q9 | D32 | D41 | R309 | R311 | SERIAL DEBUG | R312 | R310 | R313 | C437 | C427 | C426 | C436 | C433 | C5 | C12 | C11 | C6 | POWER | R8 | R7 | R35 | R36 | R1 | R34 | FL1 | D12 | D13 | R52 | FL2 | L15 | L13 | D14 | R55 | D15 | L9 | C260 | FL3 | R53 | D16 | U12 | U19 | L12 | D17 | FL4 | C100 | D18 | D19 | L5 | C261 | C104 | R54 | R406 | C477 | R260 | D20 | L14 | R232 | R219 | R271 | C101 | R66 | R270 | C103 | Q3 | C15 | R215 | L4 | R269 | R261 | R213 | R262 | C272 | R220 | R148 | R216 | U4 | D21 | R221 | R150 | R15 | R263 | C271 | C102 | R64 | R146 | L3 | R217 | R212 | R267 | R147 | D22 | R29 | R144 | R268 | R218 | R59 | R62 | R142 | R266 | R222 | R143 | R264 | R141 | R272 | R265 | R136 | D23 | R86 | R113 | C457 | R87 | R114 | C456 | R88 | R115 | L21 | C455 | R89 | R118 | R302 | R85 | R112 | R391 | C31 | R84 | R111 | R392 | C447 | C30 | R330 | C32 | C446 | R33 | R329 | R83 | R82 | R81 | C207 | R80 | R243 | C206 | R78 | R79 | R70 | R204 | C205 | C451 | C450 | R110 | R109 | R108 | R107 | C222 | R105 | C221 | R106 | C409 | C220 | R295 | C410 | C413 | C411 | C406 | C404 | C49 | R403 | C475 | D34 | C445 | R300 | R121 | C223 | R100 | R99 | R331 | R408 | R101 | R102 | R103 | D36 | R97 | R104 | R415 | R117 | R413 | R98 | R414 | R412 | R116 | R256 | R410 | C495 | R409 | C448 | R257 | C215 | R320 | C479 | R252 | R249 | R207 | R94 | R71 | R253 | C208 | C268 | C485 | C449 | R251 | R72 | R258 | C269 | R250 | R73 | R254 | R386 | C484 | C266 | R74 | R259 | R209 | C267 | REMOVE R416 WHEN | R75 | R394 | INSTALLING BATTERY | R76 | R393 | D42 | R315 | R416 | R77 | R211 | R210 | R314 | D37 | D35 | R299 | C420 | R425 | R405 | C418 | C417 | R423 | C470 | L20 | C416 | C231 | C419 | C202 | C476 | P12 | R426 | R427 | R431 | R404 | R303 | L11 | C471 | C452 | C133 | L24 | R27 | C93 | C132 | C40 | C140 | C453 | C151 | C135 | C73 | C123 | R45 | C415 | C92 | C148 | R322 | C424 | C127 | C33 | R323 | C425 | R422 | R23 | C496 | C45 | C42 | C36 | R308 | C108 | C105 | R224 | R28 | C422 | R417 | R26 | R248 | C39 | C423 | R63 | R57 | C35 | R61 | C99 | C41 | C136 | R318 | R319 | R246 | C37 | R223 | R49 | TP19 | R245 | C500 | R229 | R50 | C158 | C44 | C38 | R40 | R247 | R227 | R387 | C254 | R38 | L10 | C24 | C137 | R225 | C193 | C167 | R242 | C184 | R385 | R39 | R17 | C197 | C138 | R241 | R46 | C253 | R19 | R333 | C98 | C189 | R18 | R47 | R237 | C190 | R43 | C109 | C171 | C178 | R205 | R48 | C258 | R321 | C259 | C157 | C47 | R419 | C257 | C249 | C230 | C441 | C317 | C375 | TP16 | R418 | C316 | C374 | C315 | C329 | C373 | C370 | C311 | C328 | C334 | C368 | C362 | C388 | C310 | C326 | R279 | R281 | C367 | C386 | R372 | R284 | R349 | R280 | R361 | R283 | C291 | C305 | C360 | C346 | R343 | R340 | R374 | R373 | C325 | C290 | C385 | C345 | R352 | R342 | R378 | R375 | C289 | C304 | C359 | C344 | R355 | R354 | D10 | R364 | R379 | C303 | C357 | R346 | R356 | C288 | C340 | R371 | R365 | C352 | C384 | C324 | C299 | R336 | R337 | C287 | C302 | C356 | C351 | R368 | R380 | C339 | C298 | C383 | C323 | R357 | R339 | R370 | R382 | R341 | C301 | C355 | C309 | C366 | C382 | C322 | C314 | C331 | R360 | C358 | C372 | R351 | D11 | C286 | C300 | C354 | C381 | C338 | C321 | R350 | C277 | C281 | C10 | C278 | C320 | C349 | C280 | C378 | C380 | C333 | C285 | C294 | R282 | C337 | R278 | R348 | C308 | C365 | R275 | R277 | R362 | C275 | R363 | C276 | C282 | C279 | R376 | R344 | R353 | R377 | R367 | R345 | R347 | R366 | R381 | R369 | R358 | R338 | R359 | C216 | R383 | C438 | C379 | C332 | C297 | C343 | C431 | C296 | C313 | C330 | D8 | C342 | C353 | C371 | C439 | C263 | R407 | D9 | C478 | L22 | R236 | C3 | L23 | C14 | R332 | R384 | R240 | D27 | D26 | D25 | D33 | D31 | D38 | D28 | D30 | U43 | Q10 | U44 | C497 | Q8 | U35 | BAT1 | Q7 | P8 | S1 | P10 | P1 | P2 | P11 | P9 | S2 | P3 | P6 | U5 | U22 | U14 | P13 | P5 | U15 | P15 | SD/eMMC | SATA/SD | FAN | DC | U23 | U24 | U26 | U25 | 3.3V | 12V | GND | 5V | AUDIO OUT | AUDIO IN | U11 | AM572X | J3 | J4 | J6 | J1 | USB CLIENT | JTAG | P17 | P19 | CURRENT MON | DC IN | RESET | HDMI | uSD | USB3_1 | eSATA | USB_2/3 | 2 X ETHERNET | P18 | P16 | * | Top Side View | Bottom Side View
User.24: NONE
User.41: FIGURE | SIZE | 8.0 | 27.559 | 86.614 | DRILL CHART: TOP to BOTTOM | ALL UNITS ARE IN MILS | TOLERANCE | +3.0/-3.0 | +0.0/-0.0 | PLATED | QTY | 891 | 10 | 20 | 4 | 2
User.45: FIGURE | SIZE | 4.0 | 8.0 | DRILL CHART: TOP to GND_L2 | ALL UNITS ARE IN MILS | DRILL CHART: GND_L11 to BOTTOM | DRILL CHART: GND_L2 to INT_L3 | DRILL CHART: INT_L3 to SIG_L10 | DRILL CHART: SIG_L10 to GND_L11 | TOLERANCE | +3.0/-3.0 | PLATED | QTY | 857 | 597 | 684 | 312 | 218
